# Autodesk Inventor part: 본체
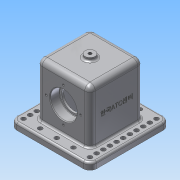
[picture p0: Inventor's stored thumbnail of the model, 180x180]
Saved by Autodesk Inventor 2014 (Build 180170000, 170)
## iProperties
Created: 2018-11
Part Number: 본체
Material: 알루미늄 6061
Document SubType Name: Modeling
Designer: user
Density: 2.71 g/cm^3
Appearance: 알루미늄 - 평지
Mass: 1020.76 g
Surface Area: 777.082 cm^2
Volume: 376.663 cm^3
Author: user
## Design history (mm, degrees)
sketch "스케치1"
  geometry: 1 further point
sketch "스케치2"
  geometry: L1 (-40, 40)-(40, 40); L2 (40, 40)-(40, -40); L3 (40, -40)-(-40, -40); L4 (-40, -40)-(-40, 40); L5 (-40, 40)-(40, -40); L6 (40, 40)-(-40, -40); 1 further point
  constraints: 12 end point, 2 midpoint, 2 parallel, 1 horizontal, 1 perpendicular
  dimensions: "d0" = 80 distance of L2.end L3.end; "d1" = 80 distance of L1.end L2.end
extrude "돌출1" new body sketch "스케치2" distance "d2" = 90; taper "d3" = 0 deg
sketch "스케치3"
  geometry: L1 (-23, 30)-(23, 30); L2 (23, 30)-(23, -30); L3 (23, -30)-(-23, -30); L4 (-23, -30)-(-23, 30); L5 (-23, 30)-(23, -30); L6 (23, 30)-(-23, -30); 1 further point
  constraints: 12 end point, 2 midpoint, 2 parallel, 1 horizontal, 1 perpendicular
  dimensions: "d4" = 46 distance of L2.end L3.end; "d5" = 60 distance of L1.end L2.end
extrude "돌출2" cut sketch "스케치3" distance "d6" = 80; taper "d7" = 0 deg
fillet "모깎기1" dims "d8" = 8
fillet "모깎기2" dims "d9" = 8
fillet "모깎기3" dims "d10" = 3
fillet "모깎기4" dims "d11" = 3
sketch "스케치4"
  geometry: L1 (32, 40)-(-32, 40) reference; L2 (-40, 32)-(-40, -32) reference; L3 (-32, -40)-(32, -40) reference; L4 (40, -32)-(40, 32) reference; L5 (-60, 60)-(60, 60); L6 (60, 60)-(60, -60); L7 (60, -60)-(-60, -60); L8 (-60, -60)-(-60, 60); L9 (-60, 60)-(60, -60); L10 (60, 60)-(-60, -60); A1 r 8 centre (32, 32) between (40, 32) and (32, 40) reference; A2 r 8 centre (-32, 32) between (-32, 40) and (-40, 32) reference; A3 r 8 centre (-32, -32) between (-40, -32) and (-32, -40) reference; A4 r 8 centre (32, -32) between (32, -40) and (40, -32) reference; 1 further point
  constraints: 12 end point, 2 midpoint, 2 parallel, 1 horizontal, 1 perpendicular
  dimensions: "d12" = 120 distance of L6.end L7.end; "d13" = 120 distance of L5.end L6.end
extrude "돌출3" join sketch "스케치4" distance "d14" = 10; taper "d15" = 0 deg
fillet "모깎기5" dims "d16" = 10
fillet "모깎기6" dims "d17" = 3
sketch "스케치6"
  geometry: L1 (82, -18)-(82, 82) reference; L2 (0, -8)-(69, -8) reference; C1 r 20 at (34, 32); 1 further point
  constraints: 1 centre point
  dimensions: "d20" = 40 diameter of C1; "d21" = 48 distance from line of L1 C1.centre; "d22" = 40 distance from line of C1.centre L2
extrude "돌출4" cut sketch "스케치6" distance "d23" = 14; taper "d24" = 0 deg
sketch "스케치7"
  geometry: C1 r 20 at (0, 0) reference; C2 r 16.5 at (0, 0); 1 further point
  constraints: 1 centre point, 1 coincident
  dimensions: "d25" = 33 diameter of C2
extrude "돌출5" cut sketch "스케치7" distance "d26" = 3; taper "d27" = 0 deg
sketch "스케치8"
  geometry: C1 r 20 at (34, 32) reference; 2 further points
  dimensions: "d28" = 26 distance of C1.centre point (8, 32)
hole "구멍1" sketch "스케치8" at (8, 32) diameter "d29" = 3.242; stored, may be unused: countersink angle "d33" = 90 deg, drill point angle "d35" = 118 deg; dims "d30" = 8, "d31" = 40, "d32" = 14, "d34" = 10
node "작업 평면1"
sketch "스케치9"
  geometry: C1 r 7.5 at (0, 0); 1 further point
  constraints: 1 centre point, 1 coincident
  dimensions: "d40" = 15 diameter of C1
extrude "돌출6" join sketch "스케치9" stored distance "d41" = 3; taper "d42" = 0 deg
fillet "모깎기7" dims "d43" = 3
hole "구멍2" diameter "d46" = 4.917; stored, may be unused: countersink angle "d50" = 90 deg, drill point angle "d52" = 118 deg; dims "d47" = 8, "d48" = 40, "d49" = 14, "d51" = 10, "d53" = 10, "d54" = 10
sketch "스케치10"
  geometry: L1 (64, 69)-(64, 0) reference; L2 (86.009, 34)-(-36.717, 34); L3 (82, 82)-(-18, 82) reference; L4 (32, 82)-(32, -36.63); 1 further point
  constraints: 4 end point, 2 perpendicular, 1 other
  dimensions: "d55" = 48 distance between parallel lines of L3 L2
feature "엠보싱1" sketch "스케치10" dims "d56" = 0.5, "d57" = 0
hole "구멍3" diameter "d60" = 6.6; stored, may be unused: countersink angle "d64" = 90 deg, drill point angle "d66" = 118 deg; dims "d58" = 10, "d59" = 10, "d61" = 8, "d62" = 40, "d63" = 14, "d65" = 10
hole "구멍4" diameter "d75" = 6.6; stored, may be unused: countersink angle "d79" = 90 deg, drill point angle "d81" = 118 deg; dims "d73" = 10, "d74" = 10, "d76" = 8, "d77" = 40, "d78" = 14, "d80" = 10
hole "구멍5" diameter "d84" = 6.6; stored, may be unused: countersink angle "d88" = 90 deg, drill point angle "d90" = 118 deg; dims "d82" = 10, "d83" = 10, "d85" = 8, "d86" = 40, "d87" = 14, "d89" = 10
hole "구멍6" diameter "d93" = 6.6; stored, may be unused: countersink angle "d97" = 90 deg, drill point angle "d99" = 118 deg; dims "d91" = 10, "d92" = 10, "d94" = 8, "d95" = 40, "d96" = 14, "d98" = 10
chamfer "모따기1" distance "d124" = 1; stored, may be unused: second distance "d125" = 2, angle "d126" = 45 deg
chamfer "모따기2" distance "d127" = 1; stored, may be unused: second distance "d128" = 2, angle "d129" = 45 deg
fillet "모깎기8" dims "d130" = 0.6
fillet "모깎기9" dims "d131" = 0.6
node "솔리드1"
mirror "대칭1"
pattern_circular "원형 패턴1" dims angle "d37" = 360 deg
mirror "대칭2"
pattern_linear "직사각형 패턴7" dims "d114" = 10
pattern_linear "직사각형 패턴8" dims "d117" = 10
pattern_linear "직사각형 패턴9" dims "d120" = 25
pattern_linear "직사각형 패턴10" dims "d123" = 25
other parameters: "d39" = 5
